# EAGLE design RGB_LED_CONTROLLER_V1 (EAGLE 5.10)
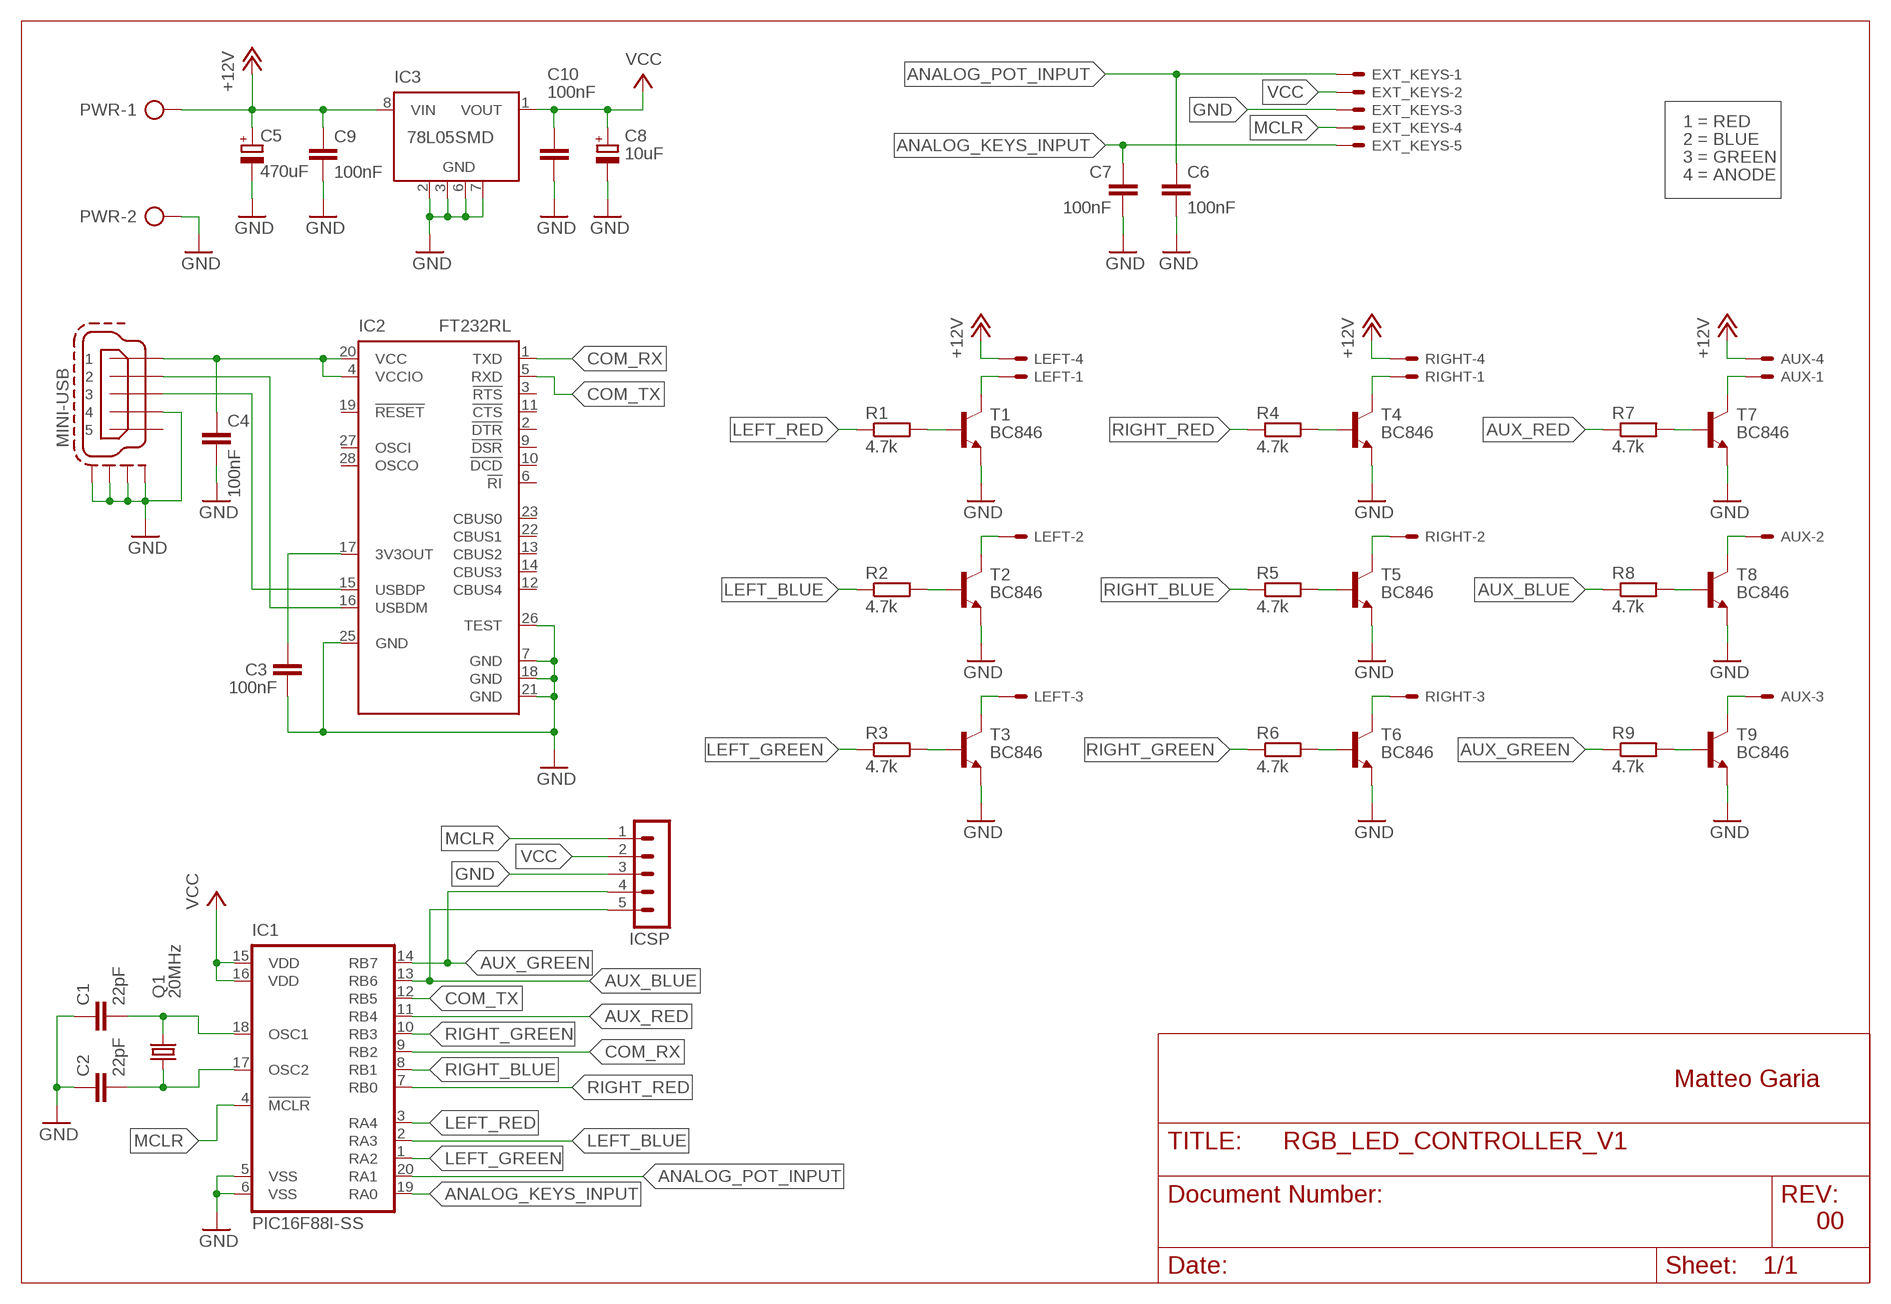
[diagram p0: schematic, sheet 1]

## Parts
AUX  22-23-2041  [22-23-2041]
C1  22pF  C-EUC0603  [C0603]
C2  22pF  C-EUC0603  [C0603]
C3  100nF  C-EUC0805  [C0805]
C4  100nF  C-EUC0805  [C0805]
C5  470uF  CPOL-EUE5-10.5  [E5-10,5]
C6  100nF  C-EUC0805  [C0805]
C7  100nF  C-EUC0805  [C0805]
C8  10uF  CPOL-EUSANYO_SMD_A5  [SANYO-OSCON_SMD_A5]
C9  100nF  C-EUC0805  [C0805]
C10  100nF  C-EUC0805  [C0805]
EXT_KEYS  22-23-2051  [22-23-2051]
IC1  PIC16F88I-SS  PIC16C58ASS-20  [SSOP20]
IC2  FT232RL  [SSOP28]
IC3  78L05SMD  [SO08]
ICSP  MA05-1  [MA05-1]
LEFT  22-23-2041  [22-23-2041]
PWR  AK500/2  [AK500/2]
Q1  20MHz  CRYSTALXTAL20SMD  [XTAL20SMD]
R1  4.7k  R-EU_R0603  [R0603]
R2  4.7k  R-EU_R0603  [R0603]
R3  4.7k  R-EU_R0603  [R0603]
R4  4.7k  R-EU_R0603  [R0603]
R5  4.7k  R-EU_R0603  [R0603]
R6  4.7k  R-EU_R0603  [R0603]
R7  4.7k  R-EU_R0603  [R0603]
R8  4.7k  R-EU_R0603  [R0603]
R9  4.7k  R-EU_R0603  [R0603]
RIGHT  22-23-2041  [22-23-2041]
T1  BC846  [SOT23]
T2  BC846  [SOT23]
T3  BC846  [SOT23]
T4  BC846  [SOT23]
T5  BC846  [SOT23]
T6  BC846  [SOT23]
T7  BC846  [SOT23]
T8  BC846  [SOT23]
T9  BC846  [SOT23]
USB  MINI-USB  MINI-USB-SCHIELD-32005-201  [32005-201]

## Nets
+12V: AUX.4 C5.+ C9.1 IC3.8(VIN) LEFT.4 PWR.1 RIGHT.4
ANALOG_KEYS_INPUT: C7.1 EXT_KEYS.5 IC1.19(RA0)
ANALOG_POT_INPUT: C6.1 EXT_KEYS.1 IC1.20(RA1)
AUX_BLUE: IC1.13(RB6) ICSP.5 R8.1
AUX_GREEN: IC1.14(RB7) ICSP.4 R9.1
AUX_RED: IC1.11(RB4) R7.1
COM_RX: IC1.9(RB2) IC2.1(TXD)
COM_TX: IC1.12(RB5) IC2.5(RXD)
GND: C1.1 C2.1 C3.2 C4.2 C5.- C6.2 C7.2 C8.- C9.2 C10.2 EXT_KEYS.3 IC1.5(VSS) IC1.6(VSS) IC2.7(GND) IC2.18(GND) IC2.21(GND) IC2.25(GND) IC2.26(TEST) IC3.2(GND) IC3.3(GND) IC3.6(GND) IC3.7(GND) ICSP.3 PWR.2 T1.2(E) T2.2(E) T3.2(E) T4.2(E) T5.2(E) T6.2(E) T7.2(E) T8.2(E) T9.2(E) USB.4 USB.M1(S:S1) USB.M2(S:S2) USB.M3(S:S3) USB.M4(S:S4)
LEFT_BLUE: IC1.2(RA3) R2.1
LEFT_GREEN: IC1.1(RA2) R3.1
LEFT_RED: IC1.3(RA4) R1.1
MCLR: EXT_KEYS.4 IC1.4(!MCLR) ICSP.1
N$1: R1.2 T1.1(B)
N$2: R4.2 T4.1(B)
N$3: R2.2 T2.1(B)
N$4: R3.2 T3.1(B)
N$5: LEFT.1 T1.3(C)
N$6: LEFT.2 T2.3(C)
N$7: LEFT.3 T3.3(C)
N$8: R5.2 T5.1(B)
N$9: R6.2 T6.1(B)
N$10: RIGHT.1 T4.3(C)
N$11: RIGHT.2 T5.3(C)
N$12: RIGHT.3 T6.3(C)
N$13: R7.2 T7.1(B)
N$14: R8.2 T8.1(B)
N$15: R9.2 T9.1(B)
N$16: AUX.1 T7.3(C)
N$17: AUX.2 T8.3(C)
N$18: AUX.3 T9.3(C)
N$19: C1.2 IC1.18(OSC1) Q1.2A
N$20: C2.2 IC1.17(OSC2) Q1.1A
N$21: C4.1 IC2.4(VCCIO) IC2.20(VCC) USB.1
N$23: IC2.15(USBDP) USB.3
N$24: IC2.16(USBDM) USB.2
N$25: C3.1 IC2.17(3V3OUT)
RIGHT_BLUE: IC1.8(RB1) R5.1
RIGHT_GREEN: IC1.10(RB3) R6.1
RIGHT_RED: IC1.7(RB0) R4.1
VCC: C8.+ C10.1 EXT_KEYS.2 IC1.15(VDD) IC1.16(VDD) IC3.1(VOUT) ICSP.2
Unconnected: IC2.2(!DTR) IC2.3(!RTS) IC2.6(!RI) IC2.9(!DSR) IC2.10(!DCD) IC2.11(!CTS) IC2.12(CBUS4) IC2.13(CBUS2) IC2.14(CBUS3) IC2.19(!RESET) IC2.22(CBUS1) IC2.23(CBUS0) IC2.27(OSCI) IC2.28(OSCO) IC3.4(NC) IC3.5(NC) USB.5

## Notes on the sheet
- 1 = RED
- 2 = BLUE
- 3 = GREEN
- 4 = ANODE
- Matteo Garia
- 00

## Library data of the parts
AUX LEFT RIGHT = con-molex:22-23-2041: .100" (2.54mm) Center Header - 4 Pin
C1-C4 C6 C7 C9 C10 = rcl:C-EU: CAPACITOR, European symbol
C5 C8 = rcl:CPOL-EU: POLARIZED CAPACITOR, European symbol
EXT_KEYS = con-molex:22-23-2051: .100" (2.54mm) Center Header - 5 Pin
IC1 = microchip:PIC16C*?-20: MICROCONTROLLER Pin compatible devices PIC16C5X family: EPROM/ROM-based PIC16C55X family: EPROM-based PIC16C6X family PIC16CE62X family: analog comparators/EEPROM data memory PIC16C7X family: A/D converter PIC16C71X family: A/D converter Pin compatible devices: PIC16C154, PIC16CR154, PIC16C156,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
IC2 = ftdichip:FT232R: Source: http://www.ftdichip.com/Documents/DataSheets/DS_FT232R_v104.pdf
IC3 = linear:78L*SMD: Positive VOLTAGE REGULATOR
ICSP = con-lstb:MA05-1: PIN HEADER
PWR = con-ptr500:AK500/2: CONNECTOR
Q1 = crystal:CRYSTAL: CRYSTAL
R1-R9 = rcl:R-EU_: RESISTOR, European symbol
T1-T9 = transistor:BC846: NPN TRANSISTOR
USB = con-cypressindustries:MINI-USB-SCHIELD-: MINI USB-B Conector Source: www.cypressindustries.com

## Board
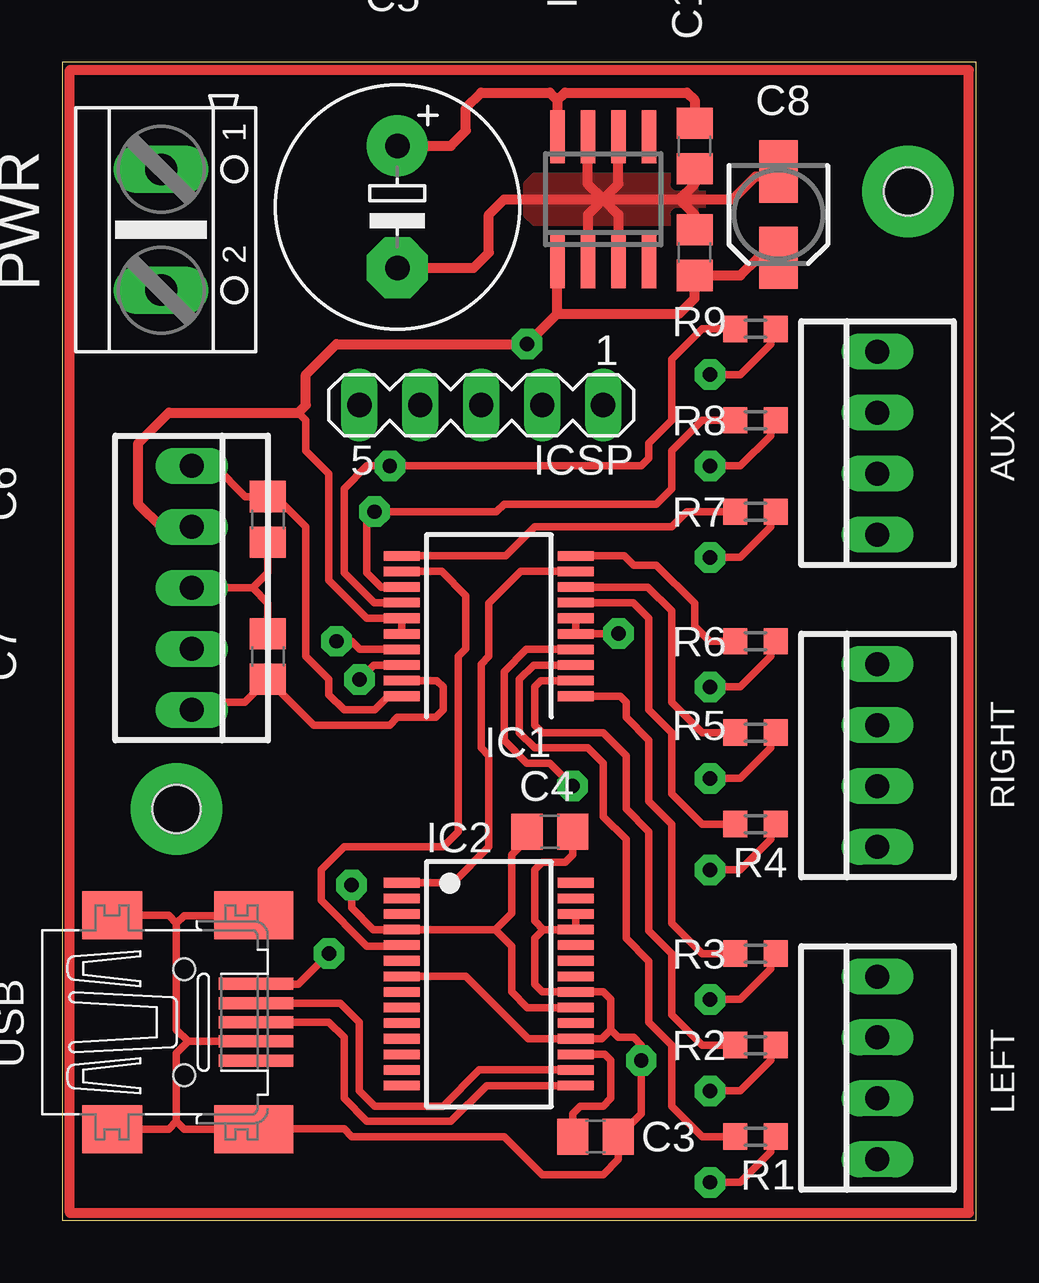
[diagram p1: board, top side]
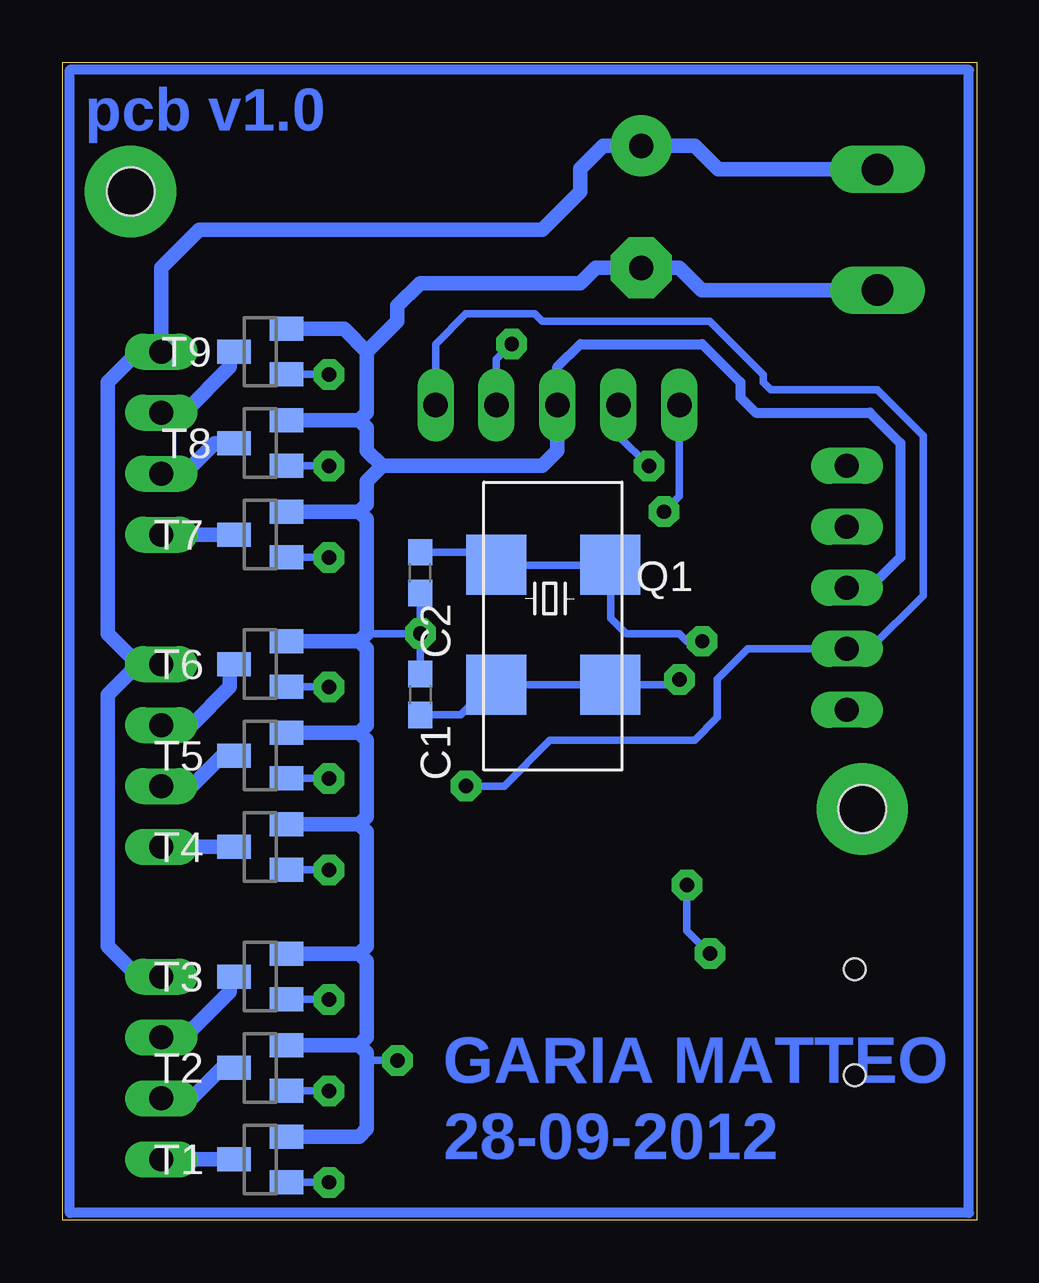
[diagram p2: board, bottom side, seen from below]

Size 38.08 x 48.25 mm. Coordinates in mm from the lower left corner, seen from the top.
Outline: 0,0 38.08,0 38.08,48.25 0,48.25 0,0
Copper layers (1*16): Top 0.035mm / dielectric 1.5mm / Bottom 0.035mm
Design rules "default": minimum track width 10mil, minimum drill 24mil, track to track 8mil, track to pad 8mil, pad to pad 8mil, via to via 8mil, smd to smd 8mil, copper to edge 40mil, drill to drill 8mil, minimum pad ring 10mil, minimum via ring 8mil, stop-mask expansion 4mil, vias tented up to drill 0mil, thermal gap 10mil
Holes 2 mm at 4.76,17.14 35.24,42.86

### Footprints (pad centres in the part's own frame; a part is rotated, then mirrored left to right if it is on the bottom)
22-23-2041 = drill 1 long: 1 -3.81,0; 2 -1.27,0; 3 1.27,0; 4 3.81,0
C0603 = smd 1.1 x 1: 1 -0.85,0; 2 0.85,0
C0805 = smd 1.3 x 1.5: 1 -0.95,0; 2 0.95,0
E5-10,5 = drill 1.016 pad 2.54 round: + -2.54,0 | drill 1.016 pad 2.54 octagon: - 2.54,0
SANYO-OSCON_SMD_A5 = smd 2.6 x 1.6: + 1.8,0; - -1.8,0
22-23-2051 = drill 1 long: 1 -5.08,0; 2 -2.54,0; 3 0,0; 4 2.54,0; 5 5.08,0
SSOP20 = smd 0.4 x 1.5: 1 -2.925,-3.625; 2 -2.275,-3.625; 3 -1.625,-3.625; 4 -0.975,-3.625; 5 -0.325,-3.625; 6 0.325,-3.625; 7 0.975,-3.625; 8 1.625,-3.625; 9 2.275,-3.625; 10 2.925,-3.625; 11 2.925,3.625; 12 2.275,3.625; 13 1.625,3.625; 14 0.975,3.625; 15 0.325,3.625; 16 -0.325,3.625; 17 -0.975,3.625; 18 -1.625,3.625; 19 -2.275,3.625; 20 -2.925,3.625
SSOP28 = smd 0.4 x 1.5: 1 -4.225,-3.625; 2 -3.575,-3.625; 3 -2.925,-3.625; 4 -2.275,-3.625; 5 -1.625,-3.625; 6 -0.975,-3.625; 7 -0.325,-3.625; 8 0.325,-3.625; 9 0.975,-3.625; 10 1.625,-3.625; 11 2.275,-3.625; 12 2.925,-3.625; 13 3.575,-3.625; 14 4.225,-3.625; 15 4.225,3.625; 16 3.575,3.625; 17 2.925,3.625; 18 2.275,3.625; 19 1.625,3.625; 20 0.975,3.625; 21 0.325,3.625; 22 -0.325,3.625; 23 -0.975,3.625; 24 -1.625,3.625; 25 -2.275,3.625; 26 -2.925,3.625; 27 -3.575,3.625; 28 -4.225,3.625
SO08 = smd 0.6 x 2.2: 1 -1.905,-2.6; 2 -0.635,-2.6; 3 0.635,-2.6; 4 1.905,-2.6; 5 1.905,2.6; 6 0.635,2.6; 7 -0.635,2.6; 8 -1.905,2.6
MA05-1 = drill 1.016 long: 1 -5.08,0; 2 -2.54,0; 3 0,0; 4 2.54,0; 5 5.08,0
AK500/2 = drill 1.321 long: 1 -2.515,0; 2 2.515,0
XTAL20SMD = smd 2.5 x 2.5: 1A -2.544,2.524; 1B -2.544,-2.226; 2A 2.456,2.524; 2B 2.456,-2.226
R0603 = smd 1 x 1.1: 1 -0.85,0; 2 0.85,0
SOT23 = smd 1 x 1.4: 1 -0.95,-1.1; 2 0.95,-1.1; 3 0,1.1
32005-201 = smd 3.1 x 0.5: 1 3,1.6; 2 3,0.8; 3 3,0; 4 3,-0.8; 5 3,-1.6 | smd 2.5 x 2: M1 -3,-4.45; M2 -3,4.45 | smd 3.3 x 2: M3 2.9,4.45; M4 2.9,-4.45 | hole 0.9: 0,2.2; 0,-2.2

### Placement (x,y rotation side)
AUX  33.97,32.38 90 top
C1  23.18,21.91 270 bottom
C2  23.18,26.99 90 bottom
C3  22.23,3.49 0 top
C4  20.32,16.19 0 top
C5  13.97,42.23 270 top
C6  8.57,29.21 270 top
C7  8.57,23.5 90 top
C8  29.84,41.91 270 top
C9  26.35,44.77 270 top
C10  26.35,40.32 90 top
EXT_KEYS  5.4,26.35 270 top
IC1  17.78,24.77 90 top
IC2  17.78,9.84 270 top
IC3  22.54,42.55 0 top
ICSP  17.46,33.97 180 top
LEFT  33.97,6.35 90 top
PWR  4.13,41.27 270 top
Q1  17.78,24.77 270 bottom
R1  28.89,3.49 0 top
R2  28.89,7.3 0 top
R3  28.89,11.11 0 top
R4  28.89,16.51 0 top
R5  28.89,20.32 0 top
R6  28.89,24.13 0 top
R7  28.89,29.53 0 top
R8  28.89,33.34 0 top
R9  28.89,37.15 0 top
RIGHT  33.97,19.37 90 top
T1  29.84,2.54 90 bottom
T2  29.84,6.35 90 bottom
T3  29.84,10.16 90 bottom
T4  29.84,15.56 90 bottom
T5  29.84,19.37 90 bottom
T6  29.84,23.18 90 bottom
T7  29.84,28.57 90 bottom
T8  29.84,32.38 90 bottom
T9  29.84,36.2 90 bottom
USB  5.08,8.26 0 top

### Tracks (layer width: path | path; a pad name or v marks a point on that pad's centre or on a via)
+12V
  Top 0.406: C9.1 26.35,46.67 26.04,46.99 20.95,46.99 20.64,46.67 | 20.64,46.67 IC3.8 | 20.64,46.67 20.32,46.99 17.46,46.99 16.83,46.35 16.83,45.4 16.19,44.77 C5.+
  Bottom 0.61: 34.92,23.18 36.2,24.45 36.2,34.92 34.92,36.2 AUX.4 33.97,39.69 32.38,41.27 18.1,41.27 16.51,42.86 16.51,43.81 15.56,44.77 C5.+ 11.75,44.77 10.77,43.79 PWR.1 | 34.92,23.18 RIGHT.4 | 34.92,23.18 36.2,21.91 36.2,11.43 34.92,10.16 LEFT.4
ANALOG_KEYS_INPUT
  Top 0.305: EXT_KEYS.5 5.71,21.59 7.62,21.59 C7.1 10.48,20.64 13.65,20.64 13.97,20.95 15.56,20.95 15.88,21.27 15.88,22.23 15.61,22.49 IC1.19
ANALOG_POT_INPUT
  Top 0.305: IC1.20 13.59,21.84 13.02,21.27 11.75,21.27 11.11,21.91 11.11,22.54 10.16,23.5 10.16,28.89 9.21,29.84 8.89,29.84 C6.1 7.62,30.16 6.35,31.43 EXT_KEYS.1
AUX_BLUE  (via drill 0.6 pad 1.27)
  Top 0.305: R8.1 26.67,33.34 25.4,32.07 25.4,30.48 24.77,29.84 18.41,29.84 18.1,29.53 v13.02,29.53 12.7,29.21 12.7,26.99 13.3,26.39 IC1.13
  Bottom 0.305: ICSP.5 12.38,30.16 v13.02,29.53
AUX_GREEN  (via drill 0.6 pad 1.27)
  Top 0.305: R9.1 26.67,37.15 25.4,35.88 25.4,33.34 24.45,32.38 24.45,31.75 24.13,31.43 v13.65,31.43 12.7,31.43 11.75,30.48 11.75,26.99 12.99,25.74 IC1.14
  Bottom 0.305: ICSP.4 14.92,32.7 v13.65,31.43
AUX_RED
  Top 0.305: R7.1 26.04,29.53 25.4,28.89 19.68,28.89 18.48,27.69 IC1.11
COM_RX
  Top 0.305: IC2.1 16.29,14.07 17.78,15.56 17.78,19.37 17.46,19.68 17.46,23.18 17.78,23.5 17.78,25.72 19.1,27.04 IC1.9
COM_TX
  Top 0.305: IC1.12 15.82,27.04 16.83,26.04 16.83,23.81 16.51,23.5 16.51,16.19 15.88,15.56 11.75,15.56 10.79,14.61 10.79,13.34 12.7,11.43 14.12,11.43 IC2.5
GND  (via drill 0.6 pad 1.27)
  Top 0.305: IC1.6 IC1.5 23.49,24.44 v23.18,24.45 | EXT_KEYS.3 7.94,26.35 | 7.94,26.35 8.57,25.72 C7.2 | C6.2 8.57,26.99 7.94,26.35 | IC2.26 IC2.25 20.05,12.12 | 22.86,7.94 22.86,9.21 22.54,9.53 IC2.21 21.4,9.53 20,9.53 19.68,9.84 19.68,11.75 20.05,12.12 | 22.86,7.94 22.49,7.57 IC2.18 19.42,7.57 16.82,10.17 IC2.7 | 22.86,7.94 23.18,7.62 23.81,7.62 24.13,7.3 v24.13,6.67 24.13,4.45 C3.2 23.18,2.54 22.54,1.91 20,1.91 18.41,3.49 12.06,3.49 11.75,3.81 USB.M4 5.08,3.81 4.76,4.13 | 20.05,12.12 19.68,12.49 19.68,14.61 20,14.92 20.95,14.92 21.27,15.24 C4.2 | 5.25,7.46 USB.4 | 5.25,7.46 4.76,7.94 4.76,12.38 | 4.76,12.38 5.08,12.7 USB.M3 | USB.M2 4.44,12.71 4.76,12.38 | 4.76,4.13 4.76,6.97 5.25,7.46 | USB.M1 4.44,3.81 4.76,4.13
  Top 0.406: IC3.3 23.18,41.91 22.54,42.55 | 22.54,42.55 21.91,41.91 IC3.2 | IC3.7 21.91,43.18 22.54,42.55 | IC3.6 23.18,43.18 22.54,42.55 | C9.2 26.35,43.18 25.72,42.55 | 22.54,42.55 25.72,42.55 | C10.2 26.35,41.91 25.72,42.55 | 25.72,42.55 27.94,42.55 28.89,43.5 29.63,43.5 C8.- | 22.54,42.55 18.41,42.55 17.78,41.91 17.78,40.32 17.14,39.69 C5.-
  Bottom 0.305: 25.4,24.45 v23.18,24.45 | v23.18,24.45 C2.1 | v23.18,24.45 C1.1 | v24.13,6.67 25.4,6.67
  Bottom 0.406: 17.46,32.07 17.46,35.56 16.51,36.51 11.43,36.51 9.84,34.92 9.84,34.29 9.21,33.66 4.45,33.66 3.17,32.38 3.17,27.62 4.45,26.35 EXT_KEYS.3
  Bottom 0.61: T9.2 26.35,37.15 25.4,36.2 | 25.4,36.2 25.4,33.66 25.72,33.34 | 25.72,33.34 25.4,33.02 25.4,32.07 24.77,31.43 | 25.72,29.53 25.4,29.84 25.4,30.8 24.77,31.43 | 25.72,29.53 25.4,29.21 25.4,24.45 25.72,24.13 | 25.72,24.13 25.4,23.81 25.4,20.64 25.72,20.32 | 25.72,20.32 25.4,20 25.4,16.83 25.72,16.51 | 25.72,16.51 25.4,16.19 25.4,11.43 25.72,11.11 | 25.72,11.11 25.4,10.79 25.4,7.62 25.72,7.3 | 25.72,7.3 25.4,6.99 25.4,6.67 25.4,3.81 25.72,3.49 T1.2 | T2.2 25.72,7.3 | T3.2 25.72,11.11 | T4.2 25.72,16.51 | T5.2 25.72,20.32 | T6.2 25.72,24.13 | T8.2 25.72,33.34 | T7.2 25.72,29.52 25.72,29.53 | ICSP.3 17.46,32.07 18.1,31.43 24.77,31.43 | 25.4,36.2 24.13,37.47 24.13,38.1 23.18,39.05 16.51,39.05 15.88,39.69 C5.- 12.38,39.69 11.46,38.76 PWR.2
  pour Top: 26.35,43.5 19.68,43.5 19.37,43.18 19.37,41.91 19.68,41.59 26.35,41.59 26.67,41.91 26.67,43.18
LEFT_BLUE
  Top 0.305: R2.1 26.67,7.3 25.4,8.57 25.4,11.11 24.45,12.06 24.45,16.19 23.5,17.14 23.5,19.37 22.54,20.32 20,20.32 19.68,20.64 19.68,22.23 19.95,22.49 IC1.2
LEFT_GREEN
  Top 0.305: R3.1 26.67,11.11 25.4,12.38 25.4,16.51 24.45,17.46 24.45,20 23.5,20.95 23.5,21.59 23.25,21.84 IC1.1
LEFT_RED
  Top 0.305: R1.1 26.67,3.49 25.4,4.76 25.4,7.3 24.45,8.26 24.45,10.79 23.5,11.75 23.5,15.88 22.54,16.83 22.54,19.05 21.91,19.68 19.68,19.68 19.05,20.32 19.05,22.54 19.65,23.14 IC1.3
MCLR  (via drill 0.6 pad 1.27)
  Top 0.305: IC1.4 19.34,23.79 18.41,22.86 18.41,20 19.37,19.05 20.32,19.05 v21.27,18.1
  Bottom 0.305: v21.27,18.1 19.68,18.1 17.78,20 11.75,20 10.79,20.95 10.79,22.54 9.53,23.81 EXT_KEYS.4 4.45,23.81 2.22,26.04 2.22,32.7 4.13,34.61 8.57,34.61 8.89,34.92 8.89,35.24 11.11,37.47 18.1,37.47 18.41,37.78 21.27,37.78 22.54,36.51 ICSP.1
N$1  (via drill 0.6 pad 1.27)
  Top 0.305: v26.99,1.59 28.26,1.59 29.53,2.86 29.53,3.28 R1.2
  Bottom 0.305: T1.1 v26.99,1.59
N$2  (via drill 0.6 pad 1.27)
  Top 0.305: v26.99,14.61 28.26,14.61 29.53,15.88 29.53,16.3 R4.2
  Bottom 0.305: T4.1 v26.99,14.61
N$3  (via drill 0.6 pad 1.27)
  Top 0.305: v26.99,5.4 28.26,5.4 29.53,6.67 29.53,7.09 R2.2
  Bottom 0.305: T2.1 v26.99,5.4
N$4  (via drill 0.6 pad 1.27)
  Top 0.305: v26.99,9.21 28.26,9.21 29.53,10.48 29.53,10.9 R3.2
  Bottom 0.305: T3.1 v26.99,9.21
N$5
  Bottom 0.61: T1.3 LEFT.1
N$6
  Bottom 0.61: LEFT.2 32.7,5.08 31.43,6.35 T2.3
N$7
  Bottom 0.61: LEFT.3 33.02,7.62 31.11,9.53 31.11,9.99 T3.3
N$8  (via drill 0.6 pad 1.27)
  Top 0.305: v26.99,18.41 28.26,18.41 29.53,19.68 29.53,20.11 R5.2
  Bottom 0.305: T5.1 v26.99,18.42 v26.99,18.41
N$9  (via drill 0.6 pad 1.27)
  Top 0.305: v26.99,22.23 28.26,22.23 29.53,23.5 29.53,23.91 R6.2
  Bottom 0.305: T6.1 v26.99,22.23
N$10
  Bottom 0.61: T4.3 RIGHT.1
N$11
  Bottom 0.61: T5.3 31.43,19.37 32.7,18.1 RIGHT.2
N$12
  Bottom 0.61: RIGHT.3 32.7,20.64 31.11,22.23 31.11,23.01 T6.3
N$13  (via drill 0.6 pad 1.27)
  Top 0.305: v26.99,27.62 28.26,27.62 29.53,28.89 29.53,29.31 R7.2
  Bottom 0.305: T7.1 v26.99,27.62
N$14  (via drill 0.6 pad 1.27)
  Top 0.305: v26.99,31.43 28.26,31.43 29.53,32.7 29.53,33.12 R8.2
  Bottom 0.305: T8.1 v26.99,31.43
N$15  (via drill 0.6 pad 1.27)
  Top 0.305: v26.99,35.24 28.26,35.24 29.53,36.51 29.53,36.93 R9.2
  Bottom 0.305: T9.1 v26.99,35.24
N$16
  Bottom 0.61: T7.3 AUX.1
N$17
  Bottom 0.61: AUX.2 33.02,31.11 31.75,32.38 T8.3
N$18
  Bottom 0.61: AUX.3 33.02,33.66 31.11,35.56 31.11,36.02 T9.3
N$19  (via drill 0.6 pad 1.27)
  Top 0.305: IC1.18 12.98,23.14 v12.38,22.54
  Bottom 0.305: Q1.2A 15.17,22.23 | Q1.2A 12.62,22.31 v12.38,22.54 | C1.2 21.49,21.06 20.24,22.31 Q1.2A
N$20  (via drill 0.6 pad 1.27)
  Top 0.305: IC1.17 12.4,23.79 12.06,24.13 v11.43,24.13
  Bottom 0.305: v11.43,24.13 12.06,24.13 12.38,24.45 14.61,24.45 15.24,25.08 15.24,27.29 Q1.1A 19.68,27.3 20.22,27.84 C2.2
N$21  (via drill 0.6 pad 1.27)
  Top 0.305: 18.05,12.12 IC2.4 12.96,12.12 12.06,13.02 v12.06,13.97 | 18.05,12.12 18.73,11.43 18.73,9.53 19.39,8.87 IC2.20 | C4.1 19.37,15.88 18.73,15.24 18.73,12.8 18.05,12.12 | v11.11,11.11 9.84,9.84 8.09,9.84 USB.1
  Bottom 0.305: v12.06,13.97 12.06,12.06 v11.11,11.11
N$22
  Bottom 0.406: 0.32,0.32 0.32,47.94 37.78,47.94 37.78,0.32 0.32,0.32
N$23
  Top 0.305: IC2.15 17.68,5.62 16.19,4.13 12.7,4.13 11.75,5.08 11.75,7.62 11.11,8.26 USB.3
N$24
  Top 0.305: IC2.16 17.38,6.27 15.88,4.76 13.02,4.76 12.38,5.4 12.38,8.26 11.58,9.05 USB.2
N$25
  Top 0.305: IC2.17 22.61,6.92 22.86,6.67 22.86,5.08 22.54,4.76 21.59,4.76 21.27,4.45 C3.1
N$26
  Top 0.406: 0.32,47.94 37.78,47.94 37.78,0.32 0.32,0.32 0.32,47.94
N$28  (via drill 2 pad 3.81)
  other vias: 35.24,42.86
N$29  (via drill 2 pad 3.81)
  other vias: 4.76,17.14
RIGHT_BLUE
  Top 0.305: IC1.8 24.41,26.39 25.4,25.4 25.4,21.59 26.67,20.32 R5.1
RIGHT_GREEN
  Top 0.305: R6.1 26.99,24.13 26.35,24.77 26.35,25.72 24.77,27.3 23.81,27.3 23.43,27.69 IC1.10
RIGHT_RED
  Top 0.305: IC1.7 23.79,25.74 24.45,25.08 24.45,21.27 25.4,20.32 25.4,17.78 26.67,16.51 R4.1
VCC  (via drill 0.6 pad 1.27)
  Top 0.305: IC1.16 IC1.15 14.15,25.08 12.7,25.08 11.11,26.67 11.11,31.11 10.16,32.07 10.16,33.34 9.84,33.66
  Top 0.406: 20.64,37.78 IC3.1 | 20.64,37.78 v19.37,36.51 11.43,36.51 10.16,35.24 10.16,33.97 9.84,33.66 4.45,33.66 3.17,32.38 3.17,29.84 4.13,28.89 EXT_KEYS.2 | 20.64,37.78 25.72,37.78 26.35,38.42 C10.1 28.26,39.37 29,40.11 C8.+
  Bottom 0.305: ICSP.2 20,35.88 v19.37,36.51

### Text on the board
Top: RGB LED CONTROLLER | TOP LAYER | PCB REV 0
Bottom: pcb v1.0 | RGB LED CONTROLLER | BOTTOM LAYER | PCB REV 0 | GARIA MATTEO | 28-09-2012
tPlace: RGB LED CONTROLLER | SILKSCREEN TOP | PCB REV. 0
bPlace: RGB LED CONTROLLER | SILKSCREEN BOT | PCB REV. 0
tValues: R1 - R9:
